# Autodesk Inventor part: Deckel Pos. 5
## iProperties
Created: 2009-11
Part Number: Deckel Pos. 5
Document SubType Name: Modeling
Designer: user
Author: user
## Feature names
1. Extrusion1
2. Bohrung1 [Hole]
